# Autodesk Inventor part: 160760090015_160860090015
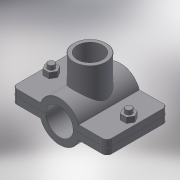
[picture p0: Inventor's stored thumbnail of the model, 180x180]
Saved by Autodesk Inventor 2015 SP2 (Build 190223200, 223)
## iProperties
Created: 2017-05
Part Number: 160760090015_160860090015
Material: Generic
Description: PLASSON SADDLE 90-1.1/2"
Document SubType Name: Modeling
Designer: KIM
Density: 1 g/cm^3
Appearance: Default
Author: KIM
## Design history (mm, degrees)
derived "16076.ipt"
feature "Solid1::16076.ipt"
feature "Solid2::16076.ipt"
tag "TaggingFeature1"
body "Solid1"
other parameters: "d0" = 99, "d1" = 141, "d2" = 45, "d4" = 105, "d5" = 0, "d6" = 7.05, "d7" = 141, "d8" = 0.1, "d10" = 0, "d11" = 0.9, "d14" = 58.2985, "d20" = 0.9, "d23" = 0.9, "d36" = 13, "d37" = 10.4, "d38" = 53, "d39" = 0, "d40" = 3, "d41" = 5, "d42" = 0, "d43" = 8, "d44" = 3, "d45" = 0, "d46" = 0.9, "d51" = 81, "d52" = 44.845, "d53" = 25, "d54" = 0, "d57" = 0, "d58" = 97.2, "d60" = 0, "d62" = 13, "d63" = 10.4, "d66" = 84.2, "G_" = 44.845, "A_" = 81, "L_" = 141, "L_1" = 105, "l_2" = 25
